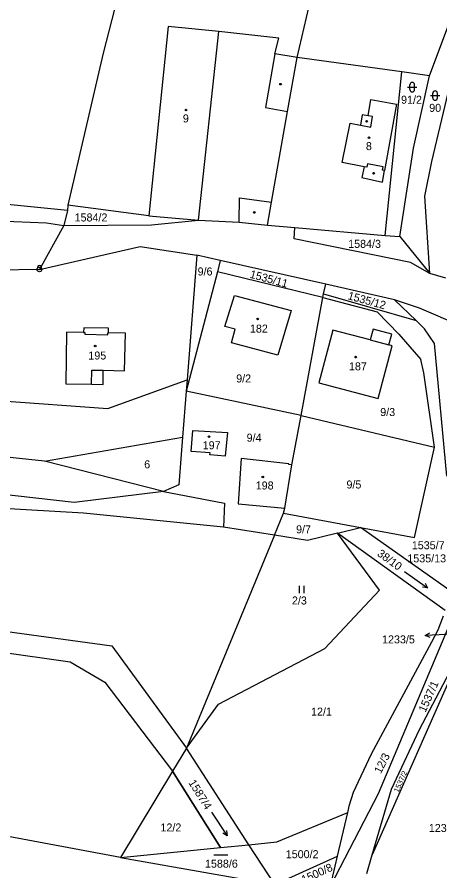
# Model space of a CAD drawing. Extents: x -801826 to -800592, y -1032871 to -1031813.
# Drawn here: x -801689.7 to -801600, y -1032403.9 to -1032222.7 of the extents above; entities that cross this region are included whole.
import ezdxf

# ---------------------------------------------------------------- set-up
doc = ezdxf.new("R2010")
doc.units = 0
for name, color, linetype in [('Vrstva 1', 7, 'Continuous'), ('Vrstva 16', 7, 'Continuous'), ('Vrstva 18', 7, 'Continuous'), ('Vrstva 19', 7, 'Continuous'), ('Vrstva 24', 7, 'Continuous'), ('Vrstva 25', 7, 'Continuous'), ('Vrstva 4', 7, 'Continuous')]:
    doc.layers.add(name, color=color, linetype=linetype)

msp = doc.modelspace()

# ---------------------------------------------------------------- linework, layer by layer
at = {"layer": 'Vrstva 1'}
for p, q in [((-801630.3, -1032231.27), (-801622.41, -1032197.71)), ((-801665.7, -1032208.11), (-801671.46, -1032230.29)), ((-801601.75, -1032253.31), (-801592.18, -1032213.05)), ((-801602.24, -1032235.1), (-801595.46, -1032216.99)), ((-801657.68, -1032224.67), (-801661.79, -1032264.85)), ((-801646.9, -1032225.75), (-801657.68, -1032224.67)), ((-801634.16, -1032227.12), (-801646.9, -1032225.75)), ((-801635, -1032230.44), (-801634.16, -1032227.12)), ((-801671.46, -1032230.29), (-801678.97, -1032262.61)), ((-801630.3, -1032231.27), (-801635, -1032230.44)), ((-801632.32, -1032242.68), (-801630.3, -1032231.27)), ((-801608.07, -1032234.3), (-801630.3, -1032231.27)), ((-801611.59, -1032269), (-801608.07, -1032234.3)), ((-801602.24, -1032235.1), (-801608.07, -1032234.3)), ((-801605.64, -1032250.46), (-801602.24, -1032235.1)), ((-801635.72, -1032261.96), (-801632.32, -1032242.68)), ((-801608.51, -1032269.26), (-801605.64, -1032250.46)), ((-801603.2, -1032260.71), (-801601.75, -1032253.31)), ((-801678.99, -1032263.72), (-801711.24, -1032260.47)), ((-801602.13, -1032277.11), (-801603.2, -1032260.71)), ((-801678.97, -1032262.61), (-801678.99, -1032263.72)), ((-801661.79, -1032264.85), (-801678.97, -1032262.61)), ((-801636.59, -1032266.86), (-801635.72, -1032261.96)), ((-801678.99, -1032263.72), (-801679.82, -1032266.92)), ((-801661.79, -1032264.85), (-801651.19, -1032265.76)), ((-801709.92, -1032265.27), (-801683.45, -1032266.31)), ((-801679.82, -1032266.92), (-801684.96, -1032276.24)), ((-801683.45, -1032266.31), (-801679.82, -1032266.92)), ((-801679.82, -1032266.92), (-801661.16, -1032266.8)), ((-801661.16, -1032266.8), (-801651.19, -1032265.76)), ((-801651.19, -1032265.76), (-801642.62, -1032266.21)), ((-801642.62, -1032266.21), (-801636.59, -1032266.86)), ((-801636.59, -1032266.86), (-801630.79, -1032267.36)), ((-801630.94, -1032269.74), (-801630.79, -1032267.36)), ((-801630.79, -1032267.36), (-801611.59, -1032269)), ((-801606.27, -1032274.79), (-801630.94, -1032269.74)), ((-801611.59, -1032269), (-801608.51, -1032269.26)), ((-801608.51, -1032269.26), (-801602.13, -1032277.11)), ((-801684.96, -1032276.24), (-801663.62, -1032271.38)), ((-801663.62, -1032271.38), (-801651.56, -1032273.23)), ((-801651.56, -1032273.23), (-801653.63, -1032299.65)), ((-801646.6, -1032274.35), (-801651.56, -1032273.23)), ((-801646.6, -1032274.35), (-801647.22, -1032276.74)), ((-801624.18, -1032279.39), (-801646.6, -1032274.35)), ((-801602.13, -1032277.11), (-801606.27, -1032274.79)), ((-801684.96, -1032276.24), (-801736.12, -1032277.15)), ((-801647.22, -1032276.74), (-801653.82, -1032302.07)), ((-801624.88, -1032282.2), (-801647.22, -1032276.74)), ((-801598.78, -1032278.08), (-801602.13, -1032277.11)), ((-801624.68, -1032281.42), (-801624.18, -1032279.39)), ((-801609.62, -1032282.66), (-801624.18, -1032279.39)), ((-801624.88, -1032282.2), (-801624.68, -1032281.42)), ((-801624.68, -1032281.42), (-801605.07, -1032287.08)), ((-801645.66, -1032288.34), (-801643.61, -1032281.8)), ((-801643.61, -1032281.8), (-801631.53, -1032284.92)), ((-801629.42, -1032307.28), (-801624.88, -1032282.2)), ((-801624.88, -1032282.2), (-801613.35, -1032285.24)), ((-801605.07, -1032287.08), (-801609.62, -1032282.66)), ((-801604.36, -1032284.46), (-801609.62, -1032282.66)), ((-801631.53, -1032284.92), (-801634.36, -1032294.46)), ((-801594.32, -1032288.81), (-801604.36, -1032284.46)), ((-801613.35, -1032285.24), (-801608.69, -1032290.01)), ((-801675.58, -1032288.6), (-801675.6, -1032289.61)), ((-801670.29, -1032288.69), (-801675.58, -1032288.6)), ((-801670.31, -1032289.7), (-801670.29, -1032288.69)), ((-801643.45, -1032288.93), (-801645.66, -1032288.34)), ((-801605.07, -1032287.08), (-801603.28, -1032288.83)), ((-801679.19, -1032289.54), (-801679.39, -1032300.49)), ((-801675.6, -1032289.61), (-801679.19, -1032289.54)), ((-801666.72, -1032289.76), (-801670.31, -1032289.7)), ((-801666.89, -1032297.74), (-801666.72, -1032289.76)), ((-801644.22, -1032291.82), (-801643.45, -1032288.93)), ((-801622.7, -1032289.11), (-801625.67, -1032300.28)), ((-801614.82, -1032291.2), (-801622.7, -1032289.11)), ((-801614.2, -1032288.92), (-801614.82, -1032291.2)), ((-801610.23, -1032289.98), (-801614.2, -1032288.92)), ((-801610.82, -1032292.25), (-801610.23, -1032289.98)), ((-801608.69, -1032290.01), (-801604.08, -1032295.36)), ((-801601.16, -1032291.94), (-801603.28, -1032288.83)), ((-801634.36, -1032294.46), (-801644.22, -1032291.82)), ((-801610.11, -1032292.44), (-801610.82, -1032292.25)), ((-801598.56, -1032320.14), (-801601.16, -1032291.94)), ((-801613.08, -1032303.62), (-801610.11, -1032292.44)), ((-801603.44, -1032298.22), (-801604.08, -1032295.36)), ((-801671.47, -1032300.66), (-801671.41, -1032297.65)), ((-801671.41, -1032297.65), (-801666.89, -1032297.74)), ((-801601.14, -1032314), (-801603.44, -1032298.22)), ((-801679.39, -1032300.49), (-801673.91, -1032300.61)), ((-801673.91, -1032300.61), (-801671.47, -1032300.66)), ((-801670.45, -1032305.78), (-801653.63, -1032299.65)), ((-801653.63, -1032299.65), (-801653.82, -1032302.07)), ((-801625.67, -1032300.28), (-801613.08, -1032303.62)), ((-801725.9, -1032301.68), (-801670.45, -1032305.78)), ((-801653.82, -1032302.07), (-801654.59, -1032311.82)), ((-801629.42, -1032307.28), (-801653.82, -1032302.07)), ((-801631.43, -1032317.72), (-801629.42, -1032307.28)), ((-801629.42, -1032307.28), (-801601.14, -1032314)), ((-801683.9, -1032316.94), (-801749.06, -1032310.16)), ((-801652.79, -1032314.88), (-801652.43, -1032310.43)), ((-801652.43, -1032310.43), (-801645.09, -1032310.85)), ((-801683.9, -1032316.94), (-801654.59, -1032311.82)), ((-801654.59, -1032311.82), (-801655.39, -1032321.96)), ((-801645.09, -1032310.85), (-801645.54, -1032315.85)), ((-801605.43, -1032333.12), (-801601.14, -1032314)), ((-801648.77, -1032315.14), (-801652.79, -1032314.88)), ((-801648.8, -1032315.6), (-801648.77, -1032315.14)), ((-801645.54, -1032315.85), (-801648.8, -1032315.6)), ((-801677.59, -1032325.75), (-801760.27, -1032316.11)), ((-801658.67, -1032323.41), (-801683.9, -1032316.94)), ((-801642.17, -1032316.39), (-801642.81, -1032326.02)), ((-801632.05, -1032317.48), (-801642.17, -1032316.39)), ((-801632.93, -1032326.92), (-801631.43, -1032317.72)), ((-801632.07, -1032317.65), (-801632.05, -1032317.48)), ((-801631.43, -1032317.72), (-801632.07, -1032317.65)), ((-801655.39, -1032321.96), (-801658.67, -1032323.41)), ((-801658.67, -1032323.41), (-801677.59, -1032325.75)), ((-801658.67, -1032323.41), (-801645.71, -1032325.85)), ((-801645.71, -1032325.85), (-801645.94, -1032330.96)), ((-801642.81, -1032326.02), (-801632.93, -1032326.92)), ((-801675.63, -1032327.96), (-801694.3, -1032326.88)), ((-801645.94, -1032330.96), (-801675.63, -1032327.96)), ((-801635.09, -1032332.67), (-801633.16, -1032328)), ((-801633.16, -1032328), (-801632.93, -1032326.92)), ((-801633.16, -1032328), (-801616.83, -1032331.02)), ((-801635.09, -1032332.67), (-801645.94, -1032330.96)), ((-801621.74, -1032332.23), (-801628.09, -1032333.8)), ((-801621.74, -1032332.23), (-801616.83, -1032331.02)), ((-801612.84, -1032344.36), (-801621.74, -1032332.23)), ((-801598.87, -1032348.64), (-801621.74, -1032332.23)), ((-801616.83, -1032331.02), (-801605.43, -1032333.12)), ((-801597.9, -1032344.43), (-801616.83, -1032331.02)), ((-801635.09, -1032332.67), (-801653.77, -1032377.9)), ((-801628.09, -1032333.8), (-801635.09, -1032332.67)), ((-801762.93, -1032343.47), (-801669.64, -1032356.14)), ((-801624.45, -1032356.7), (-801612.84, -1032344.36)), ((-801613.02, -1032387.52), (-801597.19, -1032349.85)), ((-801600.36, -1032352.73), (-801599.23, -1032349.77)), ((-801593.74, -1032353.6), (-801614.36, -1032400.55)), ((-801604.31, -1032373.94), (-801593.74, -1032353.6)), ((-801601.71, -1032355.32), (-801600.36, -1032352.73)), ((-801708.77, -1032355.22), (-801678.47, -1032359.53)), ((-801614.55, -1032379.06), (-801601.71, -1032355.32)), ((-801669.64, -1032356.14), (-801653.77, -1032377.9)), ((-801646.95, -1032368.51), (-801624.45, -1032356.7)), ((-801678.47, -1032359.53), (-801671.09, -1032363.86)), ((-801671.09, -1032363.86), (-801656.72, -1032382.79)), ((-801653.77, -1032377.9), (-801646.95, -1032368.51)), ((-801610.31, -1032386.55), (-801604.31, -1032373.94)), ((-801653.77, -1032377.9), (-801656.72, -1032382.79)), ((-801653.77, -1032377.9), (-801656.72, -1032382.79)), ((-801640.52, -1032398.37), (-801653.77, -1032377.9)), ((-801640.52, -1032398.37), (-801653.77, -1032377.9)), ((-801618.31, -1032387.18), (-801614.55, -1032379.06)), ((-801656.72, -1032382.79), (-801667.77, -1032401.12)), ((-801646.57, -1032398.98), (-801656.72, -1032382.79)), ((-801656.72, -1032382.79), (-801646.57, -1032398.98)), ((-801667.77, -1032401.12), (-801749.03, -1032385.85)), ((-801614.36, -1032400.55), (-801610.31, -1032386.55)), ((-801623.22, -1032407.17), (-801613.02, -1032387.52)), ((-801619.18, -1032389.87), (-801618.31, -1032387.18)), ((-801619.57, -1032391.52), (-801619.18, -1032389.87)), ((-801634.62, -1032397.78), (-801619.57, -1032391.52)), ((-801621.73, -1032400.79), (-801619.57, -1032391.52)), ((-801667.77, -1032401.12), (-801646.57, -1032398.98)), ((-801646.57, -1032398.98), (-801640.52, -1032398.37)), ((-801646.57, -1032398.98), (-801640.52, -1032398.37)), ((-801640.52, -1032398.37), (-801634.62, -1032397.78)), ((-801635.05, -1032406.83), (-801640.52, -1032398.37)), ((-801667.77, -1032401.12), (-801642.46, -1032405.53)), ((-801635.05, -1032406.83), (-801621.73, -1032400.79)), ((-801623.22, -1032407.17), (-801621.73, -1032400.79)), ((-801615.51, -1032404.51), (-801614.36, -1032400.55))]:
    msp.add_line(p, q, dxfattribs=at)
at = {"layer": 'Vrstva 16'}
for p, q in [((-801600.14, -1032353.78), (-801603.14, -1032353.93)), ((-801593.52, -1032353.44), (-801600.14, -1032353.78))]:
    msp.add_line(p, q, dxfattribs=at)
msp.add_lwpolyline([(-801602.11, -1032354.38), (-801603.14, -1032353.93), (-801602.16, -1032353.38)], dxfattribs=at)
at = {"layer": 'Vrstva 24'}
for radius in [0.5, 0.0364]:
    msp.add_circle((-801684.96, -1032276.24), radius, dxfattribs=at)
msp.add_arc((-801684.96, -1032275.87), 0.45, 344.4473, 196.3778, dxfattribs=at)
at = {"layer": 'Vrstva 25'}
for p, q in [((-801606.88, -1032237.54), (-801604.88, -1032237.54)), ((-801606.38, -1032238.04), (-801606.38, -1032237.04)), ((-801605.38, -1032238.04), (-801605.38, -1032237.04)), ((-801602.04, -1032239.33), (-801600.04, -1032239.33)), ((-801601.54, -1032239.83), (-801601.54, -1032238.83)), ((-801600.54, -1032239.83), (-801600.54, -1032238.83)), ((-801607.51, -1032340.36), (-801602.61, -1032343.84)), ((-801629.85, -1032343.44), (-801629.85, -1032344.94)), ((-801628.83, -1032344.94), (-801628.83, -1032343.44)), ((-801648.49, -1032391.49), (-801645.11, -1032396.45)), ((-801647.99, -1032400.53), (-801644.99, -1032400.53))]:
    msp.add_line(p, q, dxfattribs=at)
for points in [[(-801603.14, -1032342.85), (-801602.61, -1032343.84), (-801603.72, -1032343.67)], [(-801645.26, -1032395.34), (-801645.11, -1032396.45), (-801646.09, -1032395.9)]]:
    msp.add_lwpolyline(points, dxfattribs=at)
for centre in [(-801633.82, -1032236.9), (-801653.87, -1032242.4), (-801615.55, -1032244.78), (-801615.06, -1032248.29), (-801614.08, -1032255.8), (-801639.39, -1032264.14), (-801638.68, -1032286.74), (-801673.13, -1032292.5), (-801617.89, -1032294.85), (-801649, -1032311.74), (-801637.58, -1032320.29)]:
    msp.add_circle(centre, 0.175, dxfattribs=at)
for centre, start, end in [((-801605.88, -1032237.04), 0, 180), ((-801605.88, -1032238.04), 180, 0), ((-801601.04, -1032238.83), 0, 180), ((-801601.04, -1032239.83), 180, 0)]:
    msp.add_arc(centre, 0.5, start, end, dxfattribs=at)
at = {"layer": 'Vrstva 4'}
for p, q in [((-801651.19, -1032265.76), (-801646.9, -1032225.75)), ((-801635, -1032230.44), (-801637.01, -1032241.85)), ((-801615.26, -1032243.61), (-801614.64, -1032240.16)), ((-801614.64, -1032240.16), (-801609.23, -1032241.14)), ((-801609.23, -1032241.14), (-801611.76, -1032255.21)), ((-801637.01, -1032241.85), (-801632.32, -1032242.68)), ((-801616.49, -1032243.39), (-801616.89, -1032245.6)), ((-801615.26, -1032243.61), (-801616.49, -1032243.39)), ((-801620.73, -1032253.56), (-801619.06, -1032245.21)), ((-801619.06, -1032245.21), (-801616.89, -1032245.6)), ((-801614.28, -1032243.78), (-801615.26, -1032243.61)), ((-801614.68, -1032246), (-801614.28, -1032243.78)), ((-801616.89, -1032245.6), (-801614.68, -1032246)), ((-801616.05, -1032254.42), (-801620.73, -1032253.56)), ((-801615.37, -1032253.82), (-801615.5, -1032254.52)), ((-801612.08, -1032254.43), (-801615.37, -1032253.82)), ((-801616.05, -1032254.42), (-801616.57, -1032256.74)), ((-801615.5, -1032254.52), (-801616.05, -1032254.42)), ((-801612.22, -1032257.7), (-801611.76, -1032255.21)), ((-801612.21, -1032255.13), (-801612.08, -1032254.43)), ((-801611.76, -1032255.21), (-801612.21, -1032255.13)), ((-801616.57, -1032256.74), (-801612.22, -1032257.7)), ((-801642.62, -1032266.21), (-801642.51, -1032261.06)), ((-801642.51, -1032261.06), (-801635.72, -1032261.96)), ((-801675.6, -1032289.61), (-801675.34, -1032289.61)), ((-801675.34, -1032289.61), (-801675.35, -1032290.01)), ((-801675.35, -1032290.01), (-801670.45, -1032290.1)), ((-801670.45, -1032290.1), (-801670.44, -1032289.7)), ((-801670.44, -1032289.7), (-801670.31, -1032289.7)), ((-801614.82, -1032291.2), (-801610.82, -1032292.25)), ((-801673.91, -1032300.61), (-801673.85, -1032297.6)), ((-801673.85, -1032297.6), (-801671.41, -1032297.65))]:
    msp.add_line(p, q, dxfattribs=at)

# ---------------------------------------------------------------- texts
at = {"layer": 'Vrstva 16'}
for s, p in [('1535/13', (-801606.92, -1032338.43)), ('1233/5', (-801612.28, -1032355.63))]:
    msp.add_text(s, height=1.7, dxfattribs=at).set_placement(p)
at = {"layer": 'Vrstva 18'}
for s, p in [('91/2', (-801608.25, -1032241.06)), ('90', (-801602.28, -1032242.78)), ('1584/2', (-801677.5, -1032266.05)), ('1584/3', (-801619.47, -1032271.65)), ('9/6', (-801651.41, -1032277.52)), ('9/2', (-801643.22, -1032300.23)), ('9/3', (-801612.67, -1032307.36)), ('9/4', (-801641.01, -1032312.8)), ('6', (-801662.74, -1032318.46)), ('9/5', (-801619.83, -1032322.74)), ('9/7', (-801630.52, -1032332.26)), ('1535/7', (-801605.97, -1032335.64)), ('2/3', (-801631.4, -1032347.37)), ('12/1', (-801627.35, -1032370.97)), ('12/2', (-801659.29, -1032395.56)), ('1233/3', (-801602.36, -1032395.67)), ('1500/2', (-801632.71, -1032401.23)), ('1588/6', (-801649.84, -1032403.24))]:
    msp.add_text(s, height=1.7, dxfattribs=at).set_placement(p)
for s, height, rotation, p in [('1535/11', 1.7, 344.7365, (-801640.45, -1032277.96)), ('1535/12', 1.7, 344.5236, (-801619.68, -1032282.53)), ('38/10', 1.7, 324.0194, (-801613.45, -1032336.89)), ('1537/1', 1.7, 65.6832, (-801603.09, -1032370.4)), ('12/3', 1.7, 63.0147, (-801612.56, -1032383.42)), ('1537/2', 1.14, 66.6851, (-801608.8, -1032387.39)), ('1587/4', 1.7, 302.2182, (-801653.43, -1032385.21)), ('1500/8', 1.7, 24.3086, (-801628.91, -1032406.65))]:
    msp.add_text(s, height=height, rotation=rotation, dxfattribs=at).set_placement(p)
at = {"layer": 'Vrstva 19'}
for s, p in [('9', (-801654.54, -1032245.02)), ('8', (-801615.71, -1032250.9)), ('182', (-801640.31, -1032289.65)), ('195', (-801674.59, -1032295.36)), ('187', (-801619.3, -1032297.66)), ('197', (-801650.33, -1032314.41)), ('198', (-801639.08, -1032322.95))]:
    msp.add_text(s, height=1.7, dxfattribs=at).set_placement(p)

doc.saveas('drawing.dxf')
